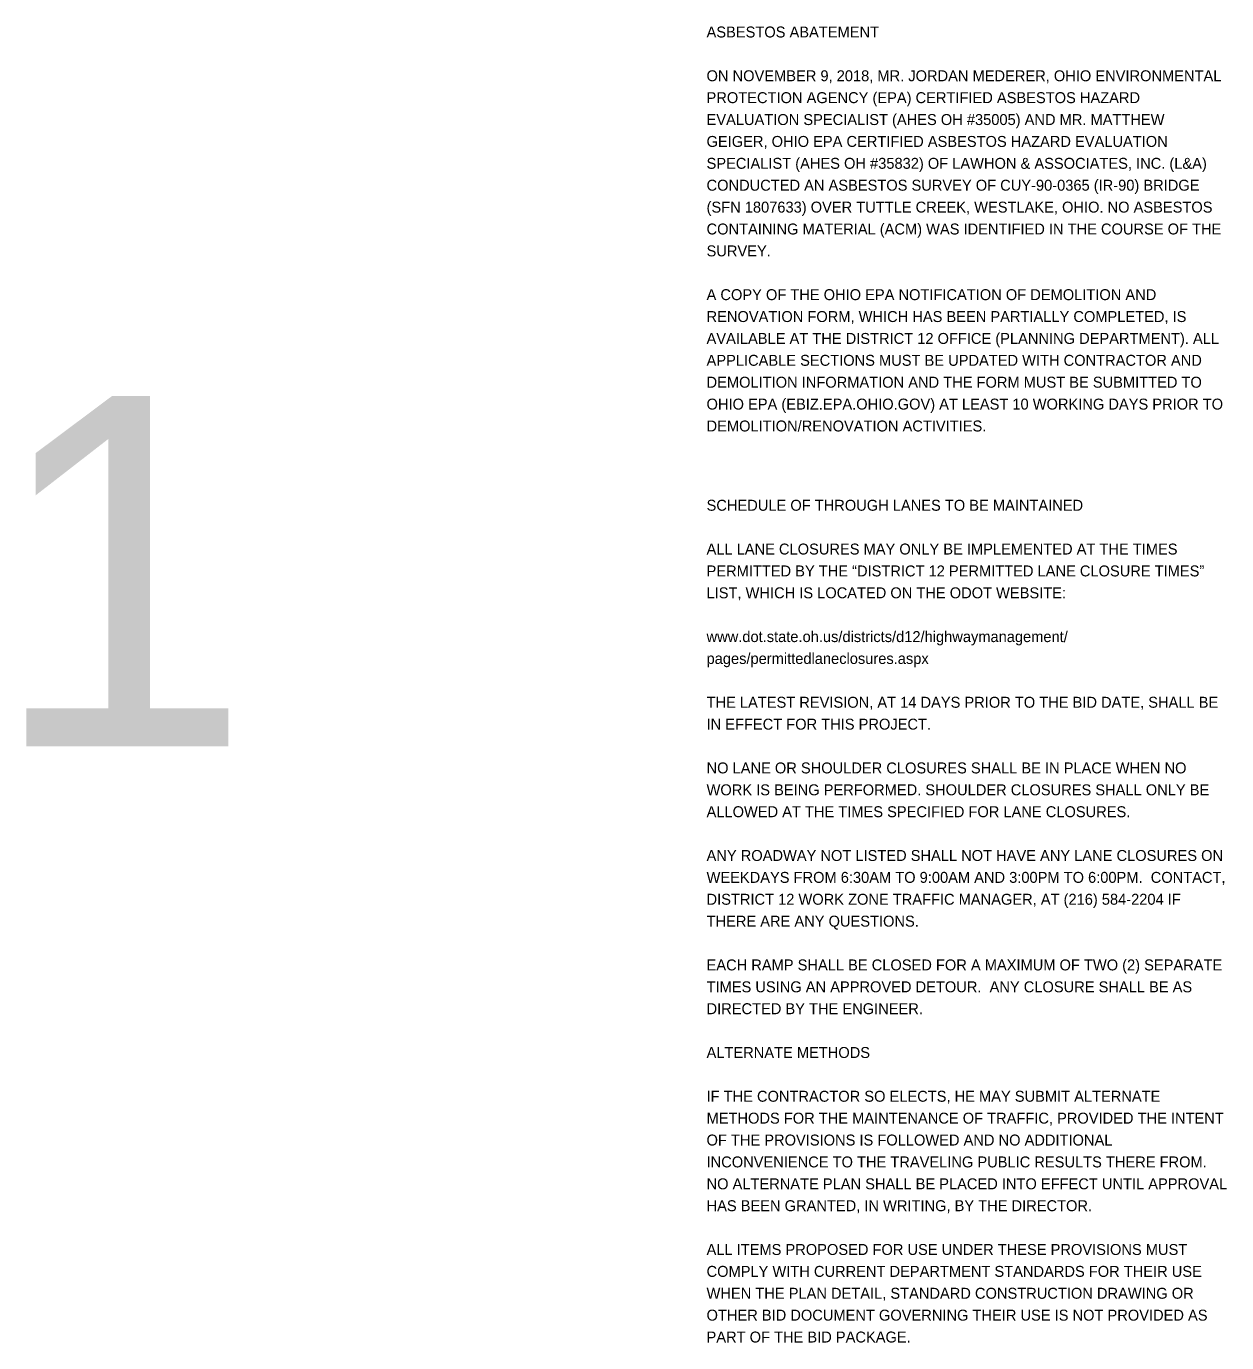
# Model space of a CAD drawing. Extents: x 0 to 2132911, y 0 to 658646.
# Drawn here: x 15.96 to 31.31, y 21.56 to 38.4 of the extents above; entities that cross this region are included whole.
import ezdxf

# ---------------------------------------------------------------- set-up
doc = ezdxf.new("R2010")
doc.units = 0
doc.layers.add('Default', color=7, linetype='Continuous')
doc.layers.add('SH_Text', color=7, linetype='Continuous')

msp = doc.modelspace()

# ---------------------------------------------------------------- texts
at = {"layer": 'Default'}
msp.add_text('1', height=4.48, dxfattribs=at).set_placement((15.504, 29.186))
at = {"layer": 'SH_Text'}
for s, p in [('ASBESTOS ABATEMENT', (24.66, 38.254)), ('ON NOVEMBER 9, 2018, MR. JORDAN MEDERER, OHIO ENVIRONMENTAL ', (24.66, 37.694)), ('PROTECTION AGENCY (EPA) CERTIFIED ASBESTOS HAZARD ', (24.66, 37.414)), ('EVALUATION SPECIALIST (AHES OH #35005) AND MR. MATTHEW ', (24.66, 37.134)), ('GEIGER, OHIO EPA CERTIFIED ASBESTOS HAZARD EVALUATION ', (24.66, 36.854)), ('SPECIALIST (AHES OH #35832) OF LAWHON & ASSOCIATES, INC. (L&A) ', (24.66, 36.574)), ('CONDUCTED AN ASBESTOS SURVEY OF CUY-90-0365 (IR-90) BRIDGE ', (24.66, 36.294)), ('(SFN 1807633) OVER TUTTLE CREEK, WESTLAKE, OHIO. NO ASBESTOS ', (24.66, 36.014)), ('CONTAINING MATERIAL (ACM) WAS IDENTIFIED IN THE COURSE OF THE ', (24.66, 35.734)), ('SURVEY. ', (24.66, 35.454)), ('A COPY OF THE OHIO EPA NOTIFICATION OF DEMOLITION AND ', (24.66, 34.894)), ('RENOVATION FORM, WHICH HAS BEEN PARTIALLY COMPLETED, IS ', (24.66, 34.614)), ('AVAILABLE AT THE DISTRICT 12 OFFICE (PLANNING DEPARTMENT). ALL ', (24.66, 34.334)), ('APPLICABLE SECTIONS MUST BE UPDATED WITH CONTRACTOR AND ', (24.66, 34.054)), ('DEMOLITION INFORMATION AND THE FORM MUST BE SUBMITTED TO ', (24.66, 33.774)), ('OHIO EPA (EBIZ.EPA.OHIO.GOV) AT LEAST 10 WORKING DAYS PRIOR TO ', (24.66, 33.494)), ('DEMOLITION/RENOVATION ACTIVITIES.', (24.66, 33.214)), ('SCHEDULE OF THROUGH LANES TO BE MAINTAINED', (24.66, 32.2)), ('ALL LANE CLOSURES MAY ONLY BE IMPLEMENTED AT THE TIMES ', (24.66, 31.64)), ('PERMITTED BY THE “DISTRICT 12 PERMITTED LANE CLOSURE TIMES” ', (24.66, 31.36)), ('LIST, WHICH IS LOCATED ON THE ODOT WEBSITE:', (24.66, 31.08)), ('www.dot.state.oh.us/districts/d12/highwaymanagement/', (24.66, 30.52)), ('pages/permittedlaneclosures.aspx', (24.66, 30.24)), ('THE LATEST REVISION, AT 14 DAYS PRIOR TO THE BID DATE, SHALL BE ', (24.66, 29.68)), ('IN EFFECT FOR THIS PROJECT.', (24.66, 29.4)), ('NO LANE OR SHOULDER CLOSURES SHALL BE IN PLACE WHEN NO ', (24.66, 28.84)), ('WORK IS BEING PERFORMED. SHOULDER CLOSURES SHALL ONLY BE ', (24.66, 28.56)), ('ALLOWED AT THE TIMES SPECIFIED FOR LANE CLOSURES. ', (24.66, 28.28)), ('ANY ROADWAY NOT LISTED SHALL NOT HAVE ANY LANE CLOSURES ON ', (24.66, 27.72)), ('WEEKDAYS FROM 6:30AM TO 9:00AM AND 3:00PM TO 6:00PM.  CONTACT, ', (24.66, 27.44)), ('DISTRICT 12 WORK ZONE TRAFFIC MANAGER, AT (216) 584-2204 IF ', (24.66, 27.16)), ('THERE ARE ANY QUESTIONS.', (24.66, 26.88)), ('EACH RAMP SHALL BE CLOSED FOR A MAXIMUM OF TWO (2) SEPARATE ', (24.66, 26.32)), ('TIMES USING AN APPROVED DETOUR.  ANY CLOSURE SHALL BE AS ', (24.66, 26.04)), ('DIRECTED BY THE ENGINEER.', (24.66, 25.76)), ('ALTERNATE METHODS', (24.66, 25.2)), ('IF THE CONTRACTOR SO ELECTS, HE MAY SUBMIT ALTERNATE ', (24.66, 24.64)), ('METHODS FOR THE MAINTENANCE OF TRAFFIC, PROVIDED THE INTENT ', (24.66, 24.36)), ('OF THE PROVISIONS IS FOLLOWED AND NO ADDITIONAL ', (24.66, 24.08)), ('INCONVENIENCE TO THE TRAVELING PUBLIC RESULTS THERE FROM. ', (24.66, 23.8)), ('NO ALTERNATE PLAN SHALL BE PLACED INTO EFFECT UNTIL APPROVAL ', (24.66, 23.52)), ('HAS BEEN GRANTED, IN WRITING, BY THE DIRECTOR.', (24.66, 23.24)), ('ALL ITEMS PROPOSED FOR USE UNDER THESE PROVISIONS MUST ', (24.66, 22.68)), ('COMPLY WITH CURRENT DEPARTMENT STANDARDS FOR THEIR USE ', (24.66, 22.4)), ('WHEN THE PLAN DETAIL, STANDARD CONSTRUCTION DRAWING OR ', (24.66, 22.12)), ('OTHER BID DOCUMENT GOVERNING THEIR USE IS NOT PROVIDED AS ', (24.66, 21.84)), ('PART OF THE BID PACKAGE.', (24.66, 21.56))]:
    msp.add_text(s, height=0.14, dxfattribs=at).set_placement(p)

doc.saveas('drawing.dxf')
